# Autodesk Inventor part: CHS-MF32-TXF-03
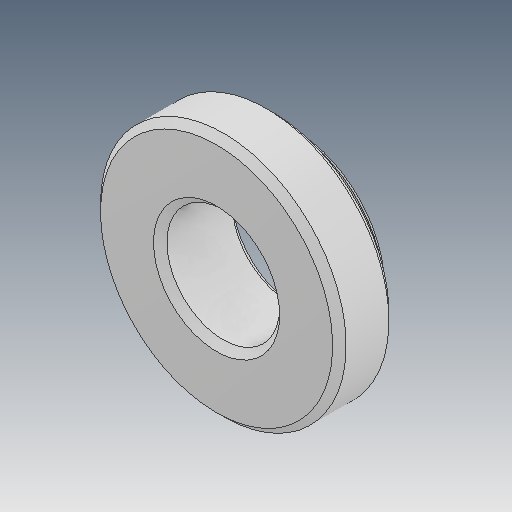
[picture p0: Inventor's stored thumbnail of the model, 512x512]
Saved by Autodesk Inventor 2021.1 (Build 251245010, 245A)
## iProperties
Created: 2021-05
Part Number: CHS-MF32-TXF-03
Material: Ogólny
Document SubType Name: Modeling
Designer: user
Density: 1 g/cm^3
Appearance: Domyślna
Author: user
Revision Number: ÈÎºÎ
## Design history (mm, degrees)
feature "ÊäÈë1"
node "Bryła1"
